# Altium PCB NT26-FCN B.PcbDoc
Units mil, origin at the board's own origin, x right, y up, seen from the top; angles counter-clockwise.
Board outline 1276.38 x 1081.1 mil, 4 copper layers (Top Layer, GND, VCC, Bottom Layer), stack 30.635 mil thick; 1 components, 0 nets, 109 pads, 0 vias.
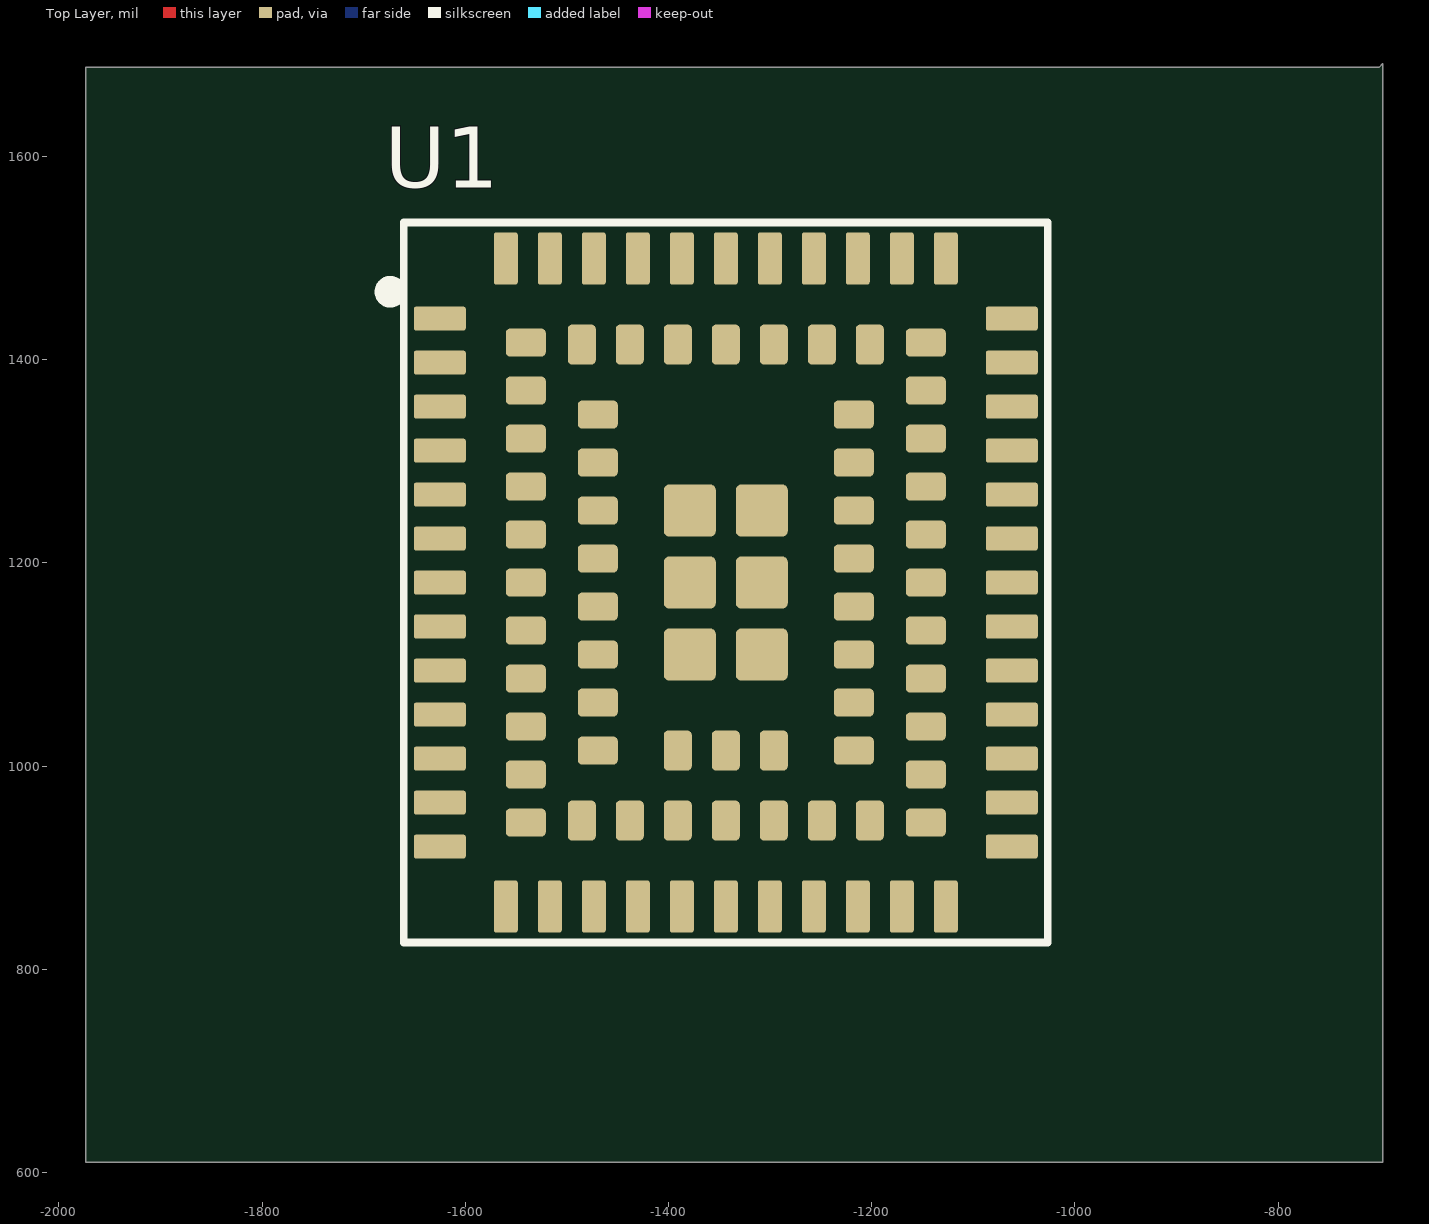
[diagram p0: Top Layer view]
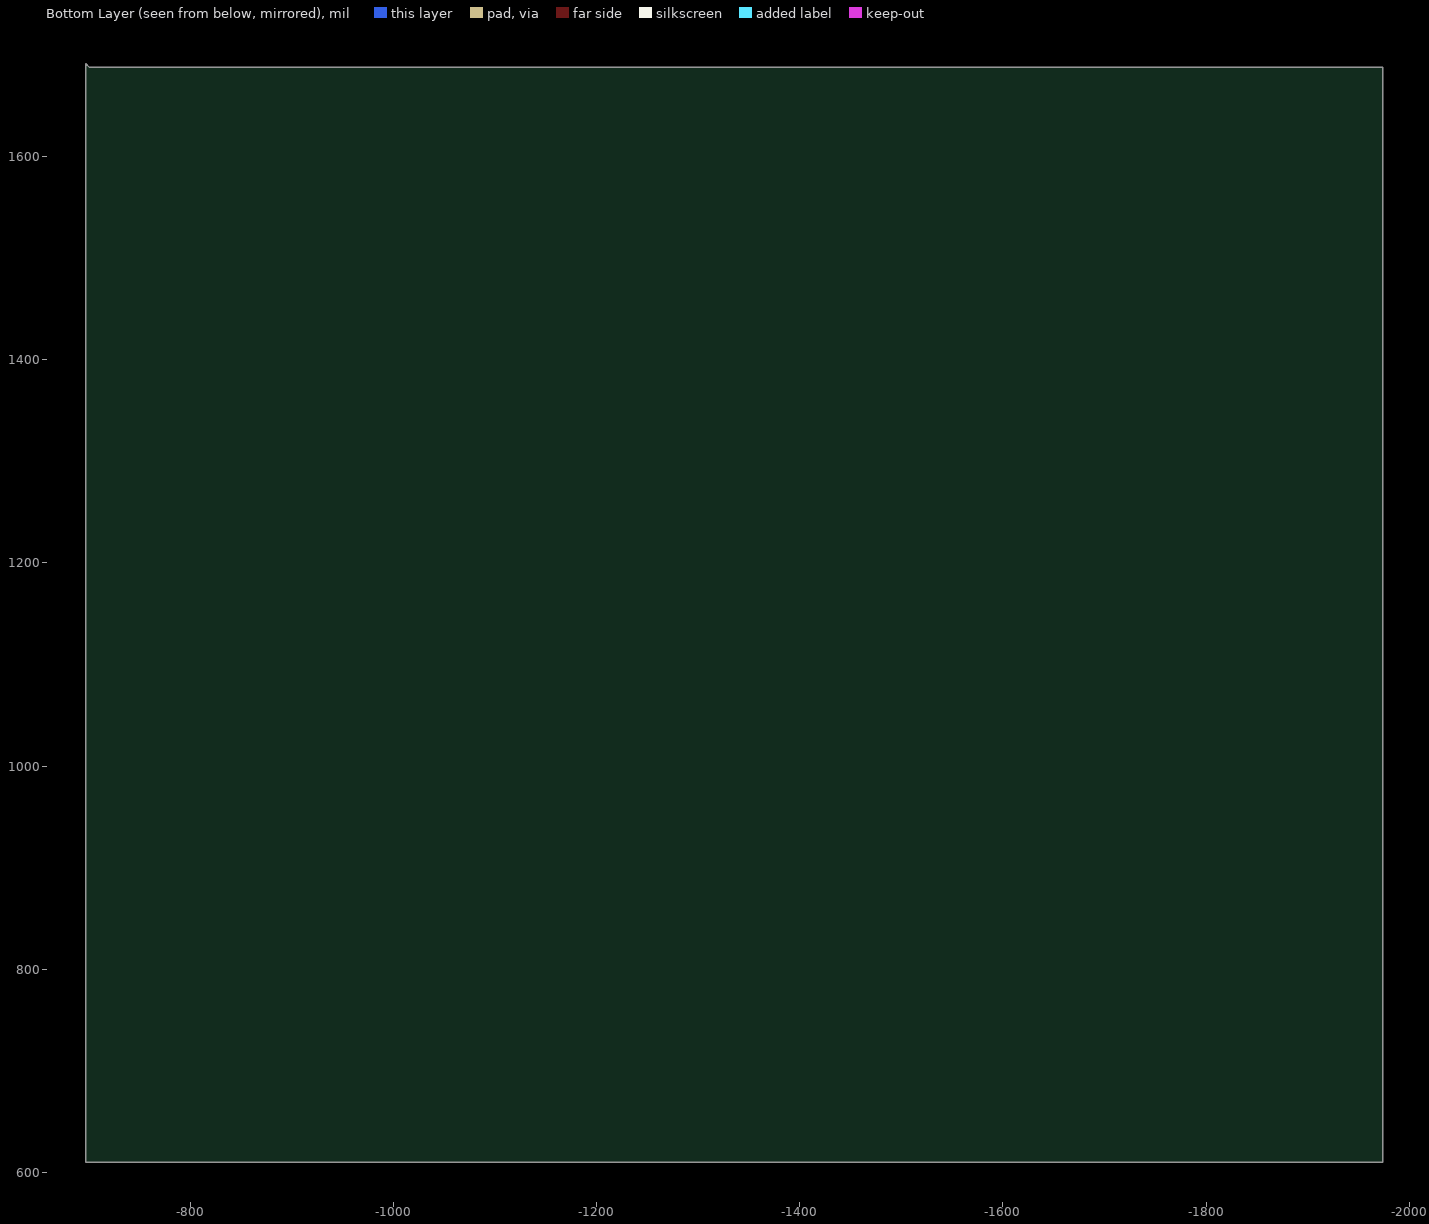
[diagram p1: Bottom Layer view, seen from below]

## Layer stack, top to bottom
Top Solder: solder mask 0.4, Solder Resist, Dk 3.5
Top Layer: signal copper 1.4
Dielectric 1: core 10, FR-4, Dk 4.2
GND: signal copper 1.4173
Dielectric 3: prepreg 5, Dk 4.2
VCC: signal copper 1.4173
Dielectric 2: core 10, Dk 4.2
Bottom Layer: signal copper 1.4
Bottom Solder: solder mask 0.4, Solder Resist, Dk 3.5

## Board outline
-1973.62,610.24 -697.24,610.24 -697.24,1691.34 -700.79,1687.8 -1973.62,1687.8
cut-out: -2812.6,1297.24

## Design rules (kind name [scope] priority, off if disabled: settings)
Clearance Clearance_polygon [InPolygon] p1: gap=7 ignorepadtopadclearanceinfootprint=FALSE except(6: Arc-Arc Arc-Track Arc-SMDPad Track-Track Track-SMDPad SMDPad-SMDPad; 10: Arc-Fill Arc-Poly Arc-Region Track-Fill Track-Poly Track-Region SMDPad-Fill SMDPad-Poly SMDPad-Region THPad-Fill THPad-Poly THPad-Region Via-Fill Via-Poly Via-Region Fill-Fill Fill-Poly Fill-Region Poly-Poly Poly-Region Region-Region)
Clearance Clearance_room [WithinRoom('LSDWNTC-LY04095001A')] p2: gap=5.9 ignorepadtopadclearanceinfootprint=FALSE except(8: Arc-Fill Arc-Poly Arc-Region Track-Fill Track-Poly Track-Region SMDPad-Fill SMDPad-Poly SMDPad-Region THPad-Fill THPad-Poly THPad-Region Via-Fill Via-Poly Via-Region Fill-Fill Fill-Poly Fill-Region Poly-Poly Poly-Region Region-Region)
Clearance Clearance_VIA [IsVia vs IsVia] p3: gap=15.75 ignorepadtopadclearanceinfootprint=FALSE
Clearance Clearance_50 [InNet('ANT')] p4: gap=8 ignorepadtopadclearanceinfootprint=FALSE
Clearance Clearance_90 [InDifferentialPair('USBD')] p5: gap=6 ignorepadtopadclearanceinfootprint=FALSE except(7: Arc-Fill Arc-Poly Arc-Region Track-Fill Track-Poly Track-Region SMDPad-Fill SMDPad-Poly SMDPad-Region THPad-Fill THPad-Poly THPad-Region Via-Fill Via-Poly Via-Region Fill-Fill Fill-Poly Fill-Region Poly-Poly Poly-Region Region-Region)
Clearance Clearance_keepout [IsKeepOut] p6: gap=14 ignorepadtopadclearanceinfootprint=FALSE except(3.94: Arc-SMDPad Track-SMDPad; 7.87: Arc-Arc Arc-Track Arc-THPad Arc-Hole Track-Track Track-THPad Track-Hole)
Clearance [All] p7: gap=7 ignorepadtopadclearanceinfootprint=FALSE except(6: Arc-Arc Arc-Track Arc-SMDPad Track-Track Track-SMDPad SMDPad-SMDPad; 8: Arc-Fill Arc-Poly Arc-Region Track-Fill Track-Poly Track-Region SMDPad-Fill SMDPad-Poly SMDPad-Region THPad-Fill THPad-Poly THPad-Region Via-Fill Via-Poly Via-Region Fill-Fill Fill-Poly Fill-Region Poly-Poly Poly-Region Region-Region)
DiffPairsRouting [All] p1: maxlimit=6 minlimit=6 mostfreqgap=6 toplayer_minwidth=9 toplayer_maxwidth=9 toplayer_prefwidth=9 midlayer1_minwidth=9 midlayer1_maxwidth=9 midlayer1_prefwidth=9 midlayer2_minwidth=9 midlayer2_maxwidth=9 midlayer2_prefwidth=9 bottomlayer_minwidth=9 bottomlayer_maxwidth=9 bottomlayer_prefwidth=9 maxuncoupledlength=500
HoleSize [All] p1: absolutevalues=TRUE maxlimit=500 minlimit=1 maxpercent=80.000 minpercent=20.000
HoleToHoleClearance [All] p1: gap=0 allowstackedmicrovias=TRUE
MinimumSolderMaskSliver [All] p1: minsoldermaskwidth=0
PolygonConnect PolygonConnect_1 [IsVia  or InComponent('D1','C1')] p1: connectstyle=Direct reliefconductorwidth=10 reliefentries=4 polygonreliefangle="90 Angle" airgapwidth=10
PolygonConnect [All] p2: thpad.connectstyle=Direct thpad.reliefconductorwidth=13.78 thpad.reliefentries=4 thpad.polygonreliefangle="90 Angle" thpad.airgapwidth=9.84 smdpad.connectstyle=Relief smdpad.reliefconductorwidth=13.78 smdpad.reliefentries=4 smdpad.polygonreliefangle="90 Angle" smdpad.airgapwidth=9.84 via.connectstyle=Direct via.reliefconductorwidth=13.78 via.reliefentries=4 via.polygonreliefangle="90 Angle" via.airgapwidth=9.84
RoutingVias [All] p1: holewidth=11.81 width=19.68 viastyle="Through Hole" minholewidth=11.81 minwidth=19.68 maxholewidth=196.85 maxwidth=314.96
ShortCircuit mark [InComponent('定位螺孔1')or InComponent('定位螺孔2')] p1:
ShortCircuit [All] p2: allowed=FALSE
SilkToSilkClearance [All] p1: silktosilkclearance=0
SilkToSolderMaskClearance [IsPad] p1: minsilkscreentomaskgap=0 clearancetoexposedcopper=TRUE
SolderMaskExpansion [All] p1: expansion=4
Width [All] p1: maxlimit=196.85 minlimit=6 preferedwidth=10
23 further rules are at their usual default settings.

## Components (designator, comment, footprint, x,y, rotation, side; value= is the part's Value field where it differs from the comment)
U1 "NT26-FCN B" "NT26-FCN B" -1343.7,1180.71 r0 top

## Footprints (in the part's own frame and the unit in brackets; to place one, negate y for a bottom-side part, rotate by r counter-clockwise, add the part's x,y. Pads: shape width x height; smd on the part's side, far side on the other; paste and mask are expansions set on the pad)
"NT26-FCN B" [mm]
  rrect20% 1.3x0.6 smd mask+0.076: 1(-7.15,6.6) 2(-7.15,5.5) 3(-7.15,4.4) 4(-7.15,3.3) 5(-7.15,2.2) 6(-7.15,1.1) 7(-7.15,0) 8(-7.15,-1.1) 9(-7.15,-2.2) 10(-7.15,-3.3) 11(-7.15,-4.4) 12(-7.15,-5.5) 13(-7.15,-6.6) 23(7.15,-6.6) 24(7.15,-5.5) 25(7.15,-4.4) 26(7.15,-3.3) 27(7.15,-2.2) 28(7.15,-1.1) 29(7.15,0) 30(7.15,1.1) 31(7.15,2.2) 32(7.15,3.3) 33(7.15,4.4) 34(7.15,5.5) 35(7.15,6.6)
  rrect20% 0.6x1.3 smd mask+0.076: 14(-4.4,-8.1) 15(-3.3,-8.1) 16(-2.2,-8.1) 17(-1.1,-8.1) 18(0,-8.1) 19(1.1,-8.1) 20(2.2,-8.1) 21(3.3,-8.1) 22(4.4,-8.1) 36(4.4,8.1) 37(3.3,8.1) 38(2.2,8.1) 39(1.1,8.1) 40(0,8.1) 41(-1.1,8.1) 42(-2.2,8.1) 43(-3.3,8.1) 44(-4.4,8.1) 95(-5.5,-8.1) 96(5.5,-8.1) 97(5.5,8.1) 98(-5.5,8.1)
  rrect30% 1x0.7 smd mask+0.064: 45(-5,4.8) 46(-5,3.6) 47(-5,2.4) 48(-5,1.2) 49(-5,0) 50(-5,-1.2) 51(-5,-2.4) 52(-5,-3.6) 53(-5,-4.8) 59(5,-4.8) 60(5,-3.6) 61(5,-2.4) 62(5,-1.2) 63(5,0) 64(5,1.2) 65(5,2.4) 66(5,3.6) 67(5,4.8) 73(-3.2,4.2) 74(-3.2,3) 75(-3.2,1.8) 76(-3.2,0.6) 77(-3.2,-0.6) 78(-3.2,-1.8) 79(-3.2,-3) 80(-3.2,-4.2) 81(3.2,-4.2) 82(3.2,-3) 83(3.2,-1.8) 84(3.2,-0.6) 85(3.2,0.6) 86(3.2,1.8) 87(3.2,3) 88(3.2,4.2) 99(-5,6) 100(-5,-6) 103(5,-6) 104(5,6)
  rrect30% 0.7x1 smd mask+0.064: 54(-2.4,-5.95) 55(-1.2,-5.95) 56(0,-5.95) 57(1.2,-5.95) 58(2.4,-5.95) 68(2.4,5.95) 69(1.2,5.95) 70(0,5.95) 71(-1.2,5.95) 72(-2.4,5.95) 101(-3.6,-5.95) 102(3.6,-5.95) 105(3.6,5.95) 106(-3.6,5.95) 107(-1.2,-4.2) 108(0,-4.2) 109(1.2,-4.2)
  rrect20% 1.3x1.3 smd mask+0.064: 89(-0.9,1.8) 90(-0.9,0) 91(-0.9,-1.8) 92(0.9,-1.8) 93(0.9,0) 94(0.9,1.8)
  silkscreen extent -8.53,-9 8.05,9

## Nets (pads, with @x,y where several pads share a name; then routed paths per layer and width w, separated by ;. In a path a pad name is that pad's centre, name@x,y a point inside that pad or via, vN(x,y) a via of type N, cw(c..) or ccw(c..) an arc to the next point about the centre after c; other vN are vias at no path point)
pads on no net: U1.1 U1.2 U1.3 U1.4 U1.5 U1.6 U1.7 U1.8 U1.9 U1.10 U1.11 U1.12 U1.13 U1.14 U1.15 U1.16 U1.17 U1.18 U1.19 U1.20 U1.21 U1.22 U1.23 U1.24 U1.25 U1.26 U1.27 U1.28 U1.29 U1.30 U1.31 U1.32 U1.33 U1.34 U1.35 U1.36 U1.37 U1.38 U1.39 U1.40 U1.41 U1.42 U1.43 U1.44 U1.45 U1.46 U1.47 U1.48 U1.49 U1.50 U1.51 U1.52 U1.53 U1.54 U1.55 U1.56 U1.57 U1.58 U1.59 U1.60 U1.61 U1.62 U1.63 U1.64 U1.65 U1.66 U1.67 U1.68 U1.69 U1.70 U1.71 U1.72 U1.73 U1.74 U1.75 U1.76 U1.77 U1.78 U1.79 U1.80 U1.81 U1.82 U1.83 U1.84 U1.85 U1.86 U1.87 U1.88 U1.89 U1.90 U1.91 U1.92 U1.93 U1.94 U1.95 U1.96 U1.97 U1.98 U1.99 U1.100 U1.101 U1.102 U1.103 U1.104 U1.105 U1.106 U1.107 U1.108 U1.109

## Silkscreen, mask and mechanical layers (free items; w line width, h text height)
Mechanical 1:
  lines w0.1: -1973.62,1687.8 -1973.62,610.24 -697.24,610.24 -697.24,1691.34 -700.79,1687.8 -1973.62,1687.8 ; -1973.62,1687.8 -1973.62,1687.8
